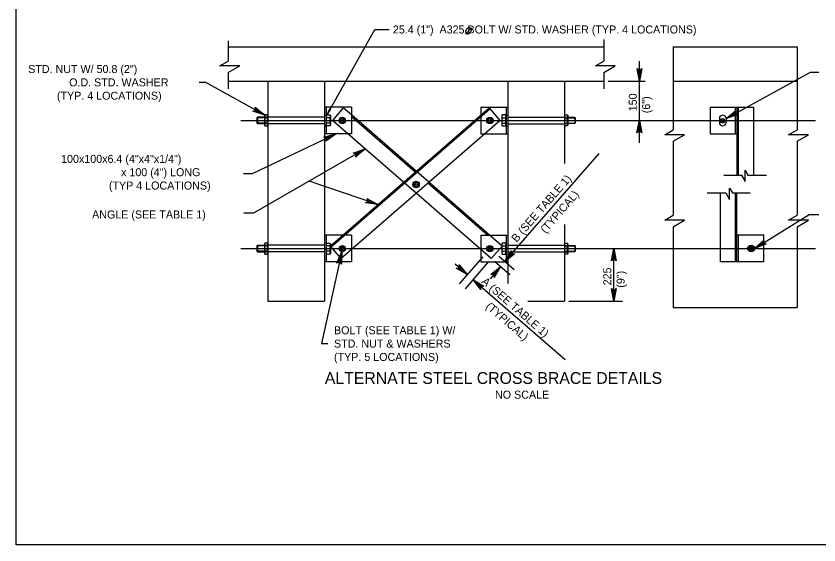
# Model space of a CAD drawing. Extents: x 638263 to 640360, y 293683 to 298655.
# Drawn here: x 639316.5 to 639617.3, y 297262.5 to 297460.7 of the extents above; entities that cross this region are included whole.
import ezdxf

# ---------------------------------------------------------------- set-up
doc = ezdxf.new("R2010")
doc.units = 0
for name, color, linetype in [('2', 7, 'Continuous'), ('3', 7, 'Continuous'), ('4', 7, 'Continuous'), ('5', 7, 'Continuous'), ('8', 7, 'Continuous')]:
    doc.layers.add(name, color=color, linetype=linetype)

msp = doc.modelspace()

# ---------------------------------------------------------------- linework, layer by layer
at = {"layer": '2'}
for p, q in [((639316.46, 297262.46), (639316.46, 297826.46)), ((640102.46, 297262.46), (639316.46, 297262.46))]:
    msp.add_line(p, q, dxfattribs=at)
at = {"layer": '3'}
for p, q in [((639450.93, 297455.71), (639456.25, 297455.71)), ((639490.65, 297416.58), (639491.98, 297416.58)), ((639491.98, 297416.58), (639500.73, 297416.58))]:
    msp.add_line(p, q, dxfattribs=at)
for points in [[(639432.73, 297423.37), (639450.93, 297455.71)], [(639550.02, 297436.36), (639549.15, 297441.02), (639549.39, 297440.67), (639549.71, 297440.48), (639550.02, 297440.43), (639550.33, 297440.48), (639550.64, 297440.67), (639550.89, 297441.02), (639550.02, 297436.36), (639550.64, 297440.67), (639550.33, 297440.48), (639550.02, 297436.36), (639550.02, 297440.43), (639549.71, 297440.48), (639550.02, 297436.36), (639549.39, 297440.67)], [(639582.5, 297422.32), (639614.1, 297439.76), (639617.31, 297439.76)], [(639550.02, 297421.6), (639550.89, 297416.94), (639550.64, 297417.3), (639550.33, 297417.48), (639550.02, 297417.54), (639549.71, 297417.48), (639549.39, 297417.3), (639549.14, 297416.94), (639550.02, 297421.6), (639549.39, 297417.3), (639549.71, 297417.48), (639550.02, 297421.6), (639550.02, 297417.54), (639550.33, 297417.48), (639550.02, 297421.6), (639550.64, 297417.3)], [(639447.29, 297410.92), (639443.68, 297407.84), (639443.87, 297408.24), (639443.87, 297408.6), (639443.76, 297408.9), (639443.56, 297409.14), (639443.25, 297409.32), (639442.81, 297409.36), (639447.29, 297410.92), (639443.25, 297409.32), (639443.56, 297409.14), (639447.29, 297410.92), (639443.76, 297408.9), (639443.87, 297408.6), (639447.29, 297410.92), (639443.87, 297408.24)], [(639452.03, 297390.07), (639426.27, 297398.84)], [(639452.03, 297390.07), (639447.34, 297390.74), (639447.76, 297390.86), (639448.03, 297391.1), (639448.18, 297391.38), (639448.23, 297391.69), (639448.16, 297392.04), (639447.9, 297392.4), (639452.03, 297390.07), (639448.16, 297392.04), (639448.23, 297391.69), (639452.03, 297390.07), (639448.18, 297391.38), (639448.03, 297391.1), (639452.03, 297390.07), (639447.76, 297390.86)], [(639593.13, 297373.57), (639613.7, 297386.35), (639617.31, 297386.35)], [(639438.5, 297372.42), (639430.87, 297337.94), (639433.34, 297337.94)], [(639438.5, 297372.42), (639438.35, 297367.68), (639438.18, 297368.08), (639437.91, 297368.33), (639437.62, 297368.45), (639437.3, 297368.46), (639436.96, 297368.35), (639436.64, 297368.05), (639438.5, 297372.42), (639436.96, 297368.35), (639437.3, 297368.46), (639438.5, 297372.42), (639437.62, 297368.45), (639437.91, 297368.33), (639438.5, 297372.42), (639438.18, 297368.08)]]:
    msp.add_lwpolyline(points, dxfattribs=at)
msp.add_lwpolyline([(639432.73, 297423.37), (639434.42, 297425.86), (639433.98, 297426.11)], close=True, dxfattribs=at)
at = {"layer": '4'}
msp.add_line((639484.85, 297453.91), (639487.09, 297456.36), dxfattribs=at)
msp.add_spline([(639486.86, 297456.12), (639486.68, 297456.25), (639486.5, 297456.3), (639486.29, 297456.32), (639486.16, 297456.32), (639485.95, 297456.27), (639485.75, 297456.18), (639485.61, 297456.1), (639485.35, 297455.89), (639485.14, 297455.62), (639485.01, 297455.37), (639484.94, 297455.14), (639484.92, 297454.92), (639484.94, 297454.74), (639485.03, 297454.47), (639485.13, 297454.34), (639485.32, 297454.19), (639485.61, 297454.12), (639485.94, 297454.13), (639486.36, 297454.32), (639486.66, 297454.58), (639486.89, 297454.9), (639487.04, 297455.23), (639487.09, 297455.6), (639487.02, 297455.84), (639486.87, 297456.12)], degree=3, dxfattribs=at)
at = {"layer": '5'}
for p, q in [((639396, 297451.41), (639396, 297443.88)), ((639536.75, 297451.93), (639536.75, 297443.88)), ((639396, 297449.16), (639536.75, 297449.16)), ((639562.71, 297449.16), (639562.71, 297418.11)), ((639562.71, 297449.16), (639609.11, 297449.16)), ((639609.11, 297449.16), (639609.11, 297418.11)), ((639392.8, 297442.03), (639396, 297443.88)), ((639400.26, 297442.03), (639392.8, 297442.03)), ((639396, 297439.57), (639400.26, 297442.03)), ((639533.55, 297442.03), (639536.75, 297443.88)), ((639541.01, 297442.03), (639533.55, 297442.03)), ((639536.75, 297439.57), (639541.01, 297442.03)), ((639396, 297439.57), (639396, 297433.46)), ((639536.75, 297439.57), (639536.75, 297433.46)), ((639396, 297436.36), (639536.75, 297436.36)), ((639410.77, 297436.36), (639410.77, 297353.88)), ((639432.03, 297436.36), (639432.03, 297353.88)), ((639500.73, 297436.36), (639500.73, 297360.44)), ((639521.99, 297436.36), (639521.99, 297405.44)), ((639562.71, 297436.36), (639609.11, 297436.36)), ((639432.03, 297426.62), (639432.03, 297416.58)), ((639442.1, 297426.62), (639432.03, 297426.62)), ((639432.65, 297426.62), (639432.65, 297416.58)), ((639434.15, 297374.52), (639493.7, 297426.29)), ((639434.47, 297374.15), (639494.02, 297425.92)), ((639439.05, 297426.29), (639434.99, 297421.62)), ((639442.1, 297423.65), (639439.05, 297426.29)), ((639442.1, 297426.62), (639442.1, 297416.58)), ((639490.65, 297426.62), (639490.65, 297423.65)), ((639490.65, 297426.62), (639500.73, 297426.62)), ((639493.7, 297426.29), (639497.77, 297421.62)), ((639500.1, 297426.62), (639500.1, 297416.58)), ((639500.73, 297426.62), (639500.73, 297416.58)), ((639576.53, 297426.62), (639592.77, 297426.62)), ((639576.53, 297426.62), (639576.53, 297416.58)), ((639585.98, 297426.62), (639585.98, 297416.58)), ((639586.57, 297426.62), (639586.57, 297401.15)), ((639587.06, 297426.62), (639587.06, 297401.15)), ((639592.77, 297426.62), (639592.77, 297401.15)), ((639400.73, 297421.6), (639532.02, 297421.6)), ((639406.89, 297422.78), (639406.73, 297422.62)), ((639406.73, 297422.62), (639406.73, 297420.58)), ((639406.89, 297422.78), (639406.89, 297420.42)), ((639410.77, 297422.78), (639406.89, 297422.78)), ((639410.77, 297422.62), (639406.89, 297422.62)), ((639409.44, 297421.6), (639410.91, 297421.6)), ((639409.74, 297423.65), (639409.59, 297423.38)), ((639409.59, 297423.38), (639409.59, 297419.83)), ((639410.77, 297422.78), (639409.59, 297422.78)), ((639410.61, 297423.65), (639409.74, 297423.65)), ((639410.61, 297422.62), (639409.74, 297422.62)), ((639410.61, 297423.65), (639410.77, 297423.38)), ((639410.77, 297423.38), (639410.77, 297419.83)), ((639432.03, 297422.85), (639410.77, 297422.85)), ((639410.77, 297422.78), (639410.77, 297420.42)), ((639432.03, 297423.57), (639432.65, 297423.57)), ((639432.65, 297422.78), (639432.6, 297422.78)), ((639432.65, 297423.37), (639432.65, 297419.83)), ((639432.73, 297423.37), (639432.65, 297423.37)), ((639432.73, 297419.56), (639432.73, 297423.65)), ((639432.73, 297423.65), (639434.09, 297423.65)), ((639434.09, 297422.62), (639432.73, 297422.62)), ((639434.09, 297423.65), (639434.25, 297423.38)), ((639434.25, 297423.38), (639434.25, 297419.83)), ((639440.78, 297416.58), (639434.99, 297421.62)), ((639438.21, 297369.84), (639497.77, 297421.62)), ((639466.38, 297402.54), (639442.1, 297423.65)), ((639466.05, 297402.17), (639442.1, 297422.99)), ((639490.65, 297422.99), (639490.65, 297416.58)), ((639498.66, 297423.65), (639498.5, 297423.38)), ((639498.5, 297423.38), (639498.5, 297419.83)), ((639500.02, 297423.65), (639498.66, 297423.65)), ((639498.66, 297422.62), (639500.02, 297422.62)), ((639500.02, 297419.56), (639500.02, 297423.65)), ((639500.02, 297423.37), (639500.1, 297423.37)), ((639500.1, 297423.57), (639500.73, 297423.57)), ((639500.1, 297423.37), (639500.1, 297419.83)), ((639500.1, 297422.78), (639500.15, 297422.78)), ((639500.73, 297422.85), (639521.99, 297422.85)), ((639523.31, 297421.6), (639521.84, 297421.6)), ((639522.14, 297423.65), (639521.99, 297423.38)), ((639521.99, 297423.38), (639521.99, 297419.83)), ((639521.99, 297422.78), (639521.99, 297420.42)), ((639521.99, 297422.78), (639523.17, 297422.78)), ((639521.99, 297422.78), (639525.86, 297422.78)), ((639521.99, 297422.62), (639525.86, 297422.62)), ((639522.14, 297423.65), (639523.01, 297423.65)), ((639522.14, 297422.62), (639523.01, 297422.62)), ((639523.01, 297423.65), (639523.17, 297423.38)), ((639523.17, 297423.38), (639523.17, 297419.83)), ((639525.86, 297422.78), (639525.86, 297420.42)), ((639525.86, 297422.78), (639526.02, 297422.62)), ((639526.02, 297422.62), (639526.02, 297420.58)), ((639532.02, 297421.6), (639615.98, 297421.6)), ((639580, 297422.32), (639580, 297420.88)), ((639582.5, 297422.32), (639582.5, 297420.88)), ((639406.73, 297420.58), (639406.89, 297420.42)), ((639410.77, 297420.58), (639406.89, 297420.58)), ((639406.89, 297420.42), (639410.77, 297420.42)), ((639410.77, 297420.42), (639409.59, 297420.42)), ((639409.59, 297419.83), (639409.74, 297419.56)), ((639410.61, 297420.58), (639409.74, 297420.58)), ((639409.74, 297419.56), (639410.61, 297419.56)), ((639410.77, 297419.83), (639410.61, 297419.56)), ((639432.03, 297420.35), (639410.77, 297420.35)), ((639432.03, 297419.63), (639432.65, 297419.63)), ((639432.65, 297420.42), (639432.6, 297420.42)), ((639434.09, 297420.58), (639432.73, 297420.58)), ((639434.09, 297419.56), (639432.73, 297419.56)), ((639434.25, 297419.83), (639434.09, 297419.56)), ((639498.5, 297419.83), (639498.66, 297419.56)), ((639498.66, 297420.58), (639500.02, 297420.58)), ((639498.66, 297419.56), (639500.02, 297419.56)), ((639500.1, 297420.42), (639500.15, 297420.42)), ((639500.1, 297419.63), (639500.73, 297419.63)), ((639500.73, 297420.35), (639521.99, 297420.35)), ((639521.99, 297420.58), (639525.86, 297420.58)), ((639521.99, 297420.42), (639523.17, 297420.42)), ((639525.86, 297420.42), (639521.99, 297420.42)), ((639521.99, 297419.83), (639522.14, 297419.56)), ((639522.14, 297420.58), (639523.01, 297420.58)), ((639523.01, 297419.56), (639522.14, 297419.56)), ((639523.17, 297419.83), (639523.01, 297419.56)), ((639526.02, 297420.58), (639525.86, 297420.42)), ((639559.51, 297416.27), (639562.71, 297418.11)), ((639605.91, 297416.27), (639609.11, 297418.11)), ((639442.1, 297416.58), (639432.03, 297416.58)), ((639461.65, 297398.43), (639440.78, 297416.58)), ((639566.98, 297416.27), (639559.51, 297416.27)), ((639562.71, 297413.8), (639566.98, 297416.27)), ((639576.53, 297416.58), (639586.57, 297416.58)), ((639613.37, 297416.27), (639605.91, 297416.27)), ((639609.11, 297413.8), (639613.37, 297416.27)), ((639562.71, 297413.8), (639562.71, 297386.06)), ((639609.11, 297413.8), (639609.11, 297386.06)), ((639589.65, 297398.74), (639589.65, 297402.95)), ((639589.65, 297402.95), (639590.7, 297401.15)), ((639471.1, 297398.43), (639466.38, 297402.54)), ((639581.65, 297401.15), (639588.26, 297401.15)), ((639588.26, 297401.15), (639589.65, 297398.74)), ((639590.7, 297401.15), (639597.69, 297401.15)), ((639466.38, 297394.32), (639461.65, 297398.43)), ((639493.18, 297378.59), (639470.78, 297398.06)), ((639493.93, 297378.59), (639471.1, 297398.43)), ((639490.65, 297373.22), (639466.38, 297394.32)), ((639575.45, 297394.42), (639582.45, 297394.42)), ((639580.37, 297368.55), (639580.37, 297394.42)), ((639582.45, 297394.42), (639583.84, 297392.02)), ((639583.84, 297396.23), (639584.88, 297394.42)), ((639583.84, 297392.02), (639583.84, 297396.23)), ((639584.88, 297394.42), (639591.49, 297394.42)), ((639586.07, 297368.55), (639586.07, 297394.42)), ((639586.57, 297368.55), (639586.57, 297394.42)), ((639559.51, 297384.21), (639562.71, 297386.06)), ((639605.91, 297384.21), (639609.11, 297386.06)), ((639521.99, 297382.62), (639521.99, 297353.88)), ((639566.98, 297384.21), (639559.51, 297384.21)), ((639562.71, 297381.75), (639566.98, 297384.21)), ((639613.37, 297384.21), (639605.91, 297384.21)), ((639609.11, 297381.75), (639613.37, 297384.21)), ((639562.71, 297381.75), (639562.71, 297351.42)), ((639609.11, 297381.75), (639609.11, 297351.42)), ((639432.03, 297378.59), (639432.03, 297368.55)), ((639438.83, 297378.59), (639432.03, 297378.59)), ((639432.65, 297378.59), (639432.65, 297368.55)), ((639442.1, 297378.59), (639439.58, 297378.59)), ((639442.1, 297378.59), (639442.1, 297373.22)), ((639490.65, 297378.59), (639490.65, 297368.55)), ((639490.65, 297378.59), (639500.73, 297378.59)), ((639498.61, 297374.52), (639493.93, 297378.59)), ((639500.1, 297378.59), (639500.1, 297368.55)), ((639500.73, 297378.59), (639500.73, 297368.55)), ((639596.61, 297378.59), (639586.57, 297378.59)), ((639587.16, 297368.55), (639587.16, 297378.59)), ((639596.61, 297368.55), (639596.61, 297378.59)), ((639400.73, 297373.57), (639532.02, 297373.57)), ((639406.89, 297374.75), (639406.73, 297374.59)), ((639406.73, 297374.59), (639406.73, 297372.55)), ((639410.77, 297374.75), (639406.89, 297374.75)), ((639406.89, 297374.75), (639406.89, 297372.39)), ((639410.77, 297374.59), (639406.89, 297374.59)), ((639409.44, 297373.57), (639410.91, 297373.57)), ((639409.74, 297375.62), (639409.59, 297375.34)), ((639409.59, 297375.34), (639409.59, 297371.79)), ((639410.77, 297374.75), (639409.59, 297374.75)), ((639410.61, 297375.62), (639409.74, 297375.62)), ((639410.61, 297374.59), (639409.74, 297374.59)), ((639410.61, 297375.62), (639410.77, 297375.34)), ((639410.77, 297375.34), (639410.77, 297371.79)), ((639432.03, 297374.82), (639410.77, 297374.82)), ((639410.77, 297374.75), (639410.77, 297372.39)), ((639432.65, 297374.75), (639432.6, 297374.75)), ((639432.65, 297375.34), (639432.65, 297371.8)), ((639432.73, 297375.34), (639432.65, 297375.34)), ((639432.73, 297371.52), (639432.73, 297375.62)), ((639432.73, 297375.62), (639434.09, 297375.62)), ((639434.09, 297374.59), (639432.73, 297374.59)), ((639434.09, 297375.62), (639434.25, 297375.34)), ((639434.15, 297374.52), (639438.21, 297369.84)), ((639434.25, 297375.34), (639434.25, 297371.79)), ((639442.1, 297373.22), (639442.1, 297368.55)), ((639494.54, 297369.84), (639490.65, 297373.22)), ((639498.61, 297374.52), (639494.54, 297369.84)), ((639498.66, 297375.62), (639498.5, 297375.34)), ((639498.5, 297375.34), (639498.5, 297371.79)), ((639500.02, 297375.62), (639498.66, 297375.62)), ((639498.66, 297374.59), (639500.02, 297374.59)), ((639500.02, 297371.52), (639500.02, 297375.62)), ((639500.02, 297375.34), (639500.1, 297375.34)), ((639500.1, 297375.34), (639500.1, 297371.8)), ((639500.1, 297374.75), (639500.15, 297374.75)), ((639500.73, 297374.82), (639521.99, 297374.82)), ((639523.31, 297373.57), (639521.84, 297373.57)), ((639522.14, 297375.62), (639521.99, 297375.34)), ((639521.99, 297375.34), (639521.99, 297371.79)), ((639521.99, 297374.75), (639521.99, 297372.39)), ((639521.99, 297374.75), (639523.17, 297374.75)), ((639521.99, 297374.75), (639525.86, 297374.75)), ((639521.99, 297374.59), (639525.86, 297374.59)), ((639522.14, 297375.62), (639523.01, 297375.62)), ((639522.14, 297374.59), (639523.01, 297374.59)), ((639523.01, 297375.62), (639523.17, 297375.34)), ((639523.17, 297375.34), (639523.17, 297371.79)), ((639525.86, 297374.75), (639525.86, 297372.39)), ((639525.86, 297374.75), (639526.02, 297374.59)), ((639526.02, 297374.59), (639526.02, 297372.55)), ((639532.02, 297373.57), (639615.98, 297373.57)), ((639406.73, 297372.55), (639406.89, 297372.39)), ((639410.77, 297372.55), (639406.89, 297372.55)), ((639406.89, 297372.39), (639410.77, 297372.39)), ((639410.77, 297372.39), (639409.59, 297372.39)), ((639409.59, 297371.79), (639409.74, 297371.52)), ((639410.61, 297372.55), (639409.74, 297372.55)), ((639409.74, 297371.52), (639410.61, 297371.52)), ((639410.77, 297371.79), (639410.61, 297371.52)), ((639432.03, 297372.32), (639410.77, 297372.32)), ((639432.65, 297372.39), (639432.6, 297372.39)), ((639434.09, 297372.55), (639432.73, 297372.55)), ((639434.09, 297371.52), (639432.73, 297371.52)), ((639434.25, 297371.79), (639434.09, 297371.52)), ((639498.5, 297371.79), (639498.66, 297371.52)), ((639498.66, 297372.55), (639500.02, 297372.55)), ((639498.66, 297371.52), (639500.02, 297371.52)), ((639500.1, 297372.39), (639500.15, 297372.39)), ((639500.73, 297372.32), (639521.99, 297372.32)), ((639521.99, 297372.55), (639525.86, 297372.55)), ((639521.99, 297372.39), (639523.17, 297372.39)), ((639525.86, 297372.39), (639521.99, 297372.39)), ((639521.99, 297371.79), (639522.14, 297371.52)), ((639522.14, 297372.55), (639523.01, 297372.55)), ((639523.01, 297371.52), (639522.14, 297371.52)), ((639523.17, 297371.79), (639523.01, 297371.52)), ((639526.02, 297372.55), (639525.86, 297372.39)), ((639442.1, 297368.55), (639432.03, 297368.55)), ((639490.65, 297368.55), (639500.73, 297368.55)), ((639596.61, 297368.55), (639580.37, 297368.55)), ((639410.77, 297353.88), (639432.03, 297353.88)), ((639508.27, 297353.88), (639521.99, 297353.88)), ((639562.71, 297351.42), (639609.11, 297351.42))]:
    msp.add_line(p, q, dxfattribs=at)
for points in [[(639409.68, 297423.54), (639387.55, 297435.88), (639385.07, 297435.88)], [(639409.68, 297423.54), (639405.18, 297425.04), (639405.62, 297425.09), (639405.93, 297425.27), (639406.13, 297425.52), (639406.24, 297425.82), (639406.22, 297426.18), (639406.03, 297426.57), (639409.68, 297423.54), (639406.22, 297426.18), (639406.24, 297425.82), (639409.68, 297423.54), (639406.13, 297425.52), (639405.93, 297425.27), (639409.68, 297423.54), (639405.62, 297425.09)], [(639436.4, 297416.58), (639404.98, 297401.64), (639401.67, 297401.64)], [(639436.4, 297416.58), (639432.56, 297413.79), (639432.78, 297414.17), (639432.81, 297414.53), (639432.73, 297414.84), (639432.55, 297415.09), (639432.25, 297415.3), (639431.81, 297415.37), (639436.4, 297416.58), (639432.25, 297415.3), (639432.55, 297415.09), (639436.4, 297416.58), (639432.73, 297414.84), (639432.81, 297414.53), (639436.4, 297416.58), (639432.78, 297414.17)], [(639447.29, 297410.92), (639405.41, 297386.84), (639401.81, 297386.84)]]:
    msp.add_lwpolyline(points, dxfattribs=at)
for centre, radius in [((639438.75, 297421.6), 1.18), ((639438.75, 297421.6), 0.833), ((639438.75, 297421.6), 0.417), ((639494, 297421.6), 1.18), ((639494, 297421.6), 0.833), ((639494, 297421.6), 0.417), ((639581.22, 297421.47), 0.833), ((639581.22, 297421.47), 0.417), ((639466.38, 297397.58), 1.18), ((639466.38, 297397.58), 0.833), ((639466.38, 297397.58), 0.417), ((639438.75, 297373.57), 1.18), ((639438.75, 297373.57), 0.833), ((639438.75, 297373.57), 0.417), ((639494, 297373.57), 1.18), ((639494, 297373.57), 0.833), ((639494, 297373.57), 0.417), ((639591.88, 297373.57), 1.25), ((639591.88, 297373.57), 0.833), ((639591.88, 297373.57), 0.417)]:
    msp.add_circle(centre, radius, dxfattribs=at)
for centre, radius, start, end in [((639410.5, 297423.13), 0.915, 146, 214), ((639413.01, 297421.6), 3.42, 162.6175, 197.3825), ((639409.85, 297423.13), 0.915, 326, 34), ((639407.34, 297421.6), 3.42, 342.6175, 17.3825), ((639433.34, 297423.13), 0.915, 326, 34), ((639430.83, 297421.6), 3.42, 342.6175, 17.3825), ((639499.42, 297423.13), 0.915, 146, 214), ((639501.93, 297421.6), 3.42, 162.6175, 197.3825), ((639522.9, 297423.13), 0.915, 146, 214), ((639525.41, 297421.6), 3.42, 162.6175, 197.3825), ((639522.25, 297423.13), 0.915, 326, 34), ((639519.74, 297421.6), 3.42, 342.6175, 17.3825), ((639581.25, 297422.32), 1.25, 0, 180), ((639410.5, 297420.07), 0.915, 146, 214), ((639409.85, 297420.07), 0.915, 326, 34), ((639433.34, 297420.07), 0.915, 326, 34), ((639499.42, 297420.07), 0.915, 146, 214), ((639522.9, 297420.07), 0.915, 146, 214), ((639522.25, 297420.07), 0.915, 326, 34), ((639581.25, 297420.88), 1.25, 180, 0), ((639410.5, 297375.1), 0.915, 146, 214), ((639413.01, 297373.57), 3.42, 162.6175, 197.3825), ((639409.85, 297375.1), 0.915, 326, 34), ((639407.34, 297373.57), 3.42, 342.6175, 17.3825), ((639433.34, 297375.1), 0.915, 326, 34), ((639430.83, 297373.57), 3.42, 342.6175, 17.3825), ((639499.42, 297375.1), 0.915, 146, 214), ((639501.93, 297373.57), 3.42, 162.6175, 197.3825), ((639522.9, 297375.1), 0.915, 146, 214), ((639525.41, 297373.57), 3.42, 162.6175, 197.3825), ((639522.25, 297375.1), 0.915, 326, 34), ((639519.74, 297373.57), 3.42, 342.6175, 17.3825), ((639410.5, 297372.03), 0.915, 146, 214), ((639409.85, 297372.03), 0.915, 326, 34), ((639433.34, 297372.03), 0.915, 326, 34), ((639499.42, 297372.03), 0.915, 146, 214), ((639522.9, 297372.03), 0.915, 146, 214), ((639522.25, 297372.03), 0.915, 326, 34)]:
    msp.add_arc(centre, radius, start, end, dxfattribs=at)
at = {"layer": '8'}
for p, q in [((639550.02, 297413.16), (639550.02, 297443.77)), ((639538.31, 297436.36), (639552.16, 297436.36)), ((639538.31, 297421.6), (639552.16, 297421.6)), ((639499.65, 297368.66), (639534.97, 297409.27)), ((639523.55, 297373.57), (639541.46, 297373.57)), ((639540.46, 297353.88), (639540.46, 297373.57)), ((639491.36, 297370.53), (639482.55, 297360.4)), ((639497.33, 297370.67), (639503.05, 297365.7)), ((639485.5, 297363.79), (639480.97, 297367.73)), ((639493.51, 297368.66), (639484.7, 297358.52)), ((639498.04, 297366.8), (639494.1, 297362.27)), ((639495.72, 297368.81), (639501.44, 297363.84)), ((639487.66, 297361.92), (639522.16, 297331.92)), ((639523.55, 297353.88), (639543.76, 297353.88))]:
    msp.add_line(p, q, dxfattribs=at)
for points in [[(639582.5, 297422.32), (639586.16, 297425.34), (639585.97, 297424.94), (639585.95, 297424.58), (639586.06, 297424.28), (639586.26, 297424.03), (639586.57, 297423.85), (639587, 297423.81), (639582.5, 297422.32), (639586.57, 297423.85), (639586.26, 297424.03), (639582.5, 297422.32), (639586.06, 297424.28), (639585.95, 297424.58), (639582.5, 297422.32), (639585.97, 297424.94)], [(639593.13, 297373.57), (639596.63, 297376.77), (639596.46, 297376.37), (639596.46, 297376.01), (639596.58, 297375.71), (639596.79, 297375.48), (639597.12, 297375.31), (639597.55, 297375.29), (639593.13, 297373.57), (639597.12, 297375.31), (639596.79, 297375.48), (639593.13, 297373.57), (639596.58, 297375.71), (639596.46, 297376.01), (639593.13, 297373.57), (639596.46, 297376.37)], [(639540.46, 297373.57), (639541.34, 297368.91), (639541.09, 297369.27), (639540.78, 297369.45), (639540.46, 297369.51), (639540.15, 297369.45), (639539.84, 297369.27), (639539.59, 297368.91), (639540.46, 297373.57), (639539.84, 297369.27), (639540.15, 297369.45), (639540.46, 297373.57), (639540.46, 297369.51), (639540.78, 297369.45), (639540.46, 297373.57), (639541.09, 297369.27)], [(639499.65, 297368.66), (639502.05, 297372.74), (639502, 297372.31), (639502.12, 297371.97), (639502.32, 297371.72), (639502.59, 297371.56), (639502.95, 297371.49), (639503.37, 297371.6), (639499.65, 297368.66), (639502.95, 297371.49), (639502.59, 297371.56), (639499.65, 297368.66), (639502.32, 297371.72), (639502.12, 297371.97), (639499.65, 297368.66), (639502, 297372.31)], [(639485.5, 297363.79), (639481.41, 297366.19), (639481.85, 297366.14), (639482.19, 297366.26), (639482.44, 297366.46), (639482.6, 297366.73), (639482.66, 297367.09), (639482.56, 297367.51), (639485.5, 297363.79), (639482.66, 297367.09), (639482.6, 297366.73), (639485.5, 297363.79), (639482.44, 297366.46), (639482.19, 297366.26), (639485.5, 297363.79), (639481.85, 297366.14)], [(639498.04, 297366.8), (639495.64, 297362.71), (639495.69, 297363.14), (639495.57, 297363.49), (639495.37, 297363.73), (639495.1, 297363.89), (639494.75, 297363.96), (639494.32, 297363.85), (639498.04, 297366.8), (639494.75, 297363.96), (639495.1, 297363.89), (639498.04, 297366.8), (639495.37, 297363.73), (639495.57, 297363.49), (639498.04, 297366.8), (639495.69, 297363.14)], [(639487.66, 297361.92), (639491.75, 297359.52), (639491.31, 297359.57), (639490.97, 297359.46), (639490.72, 297359.26), (639490.56, 297358.98), (639490.49, 297358.63), (639490.6, 297358.21), (639487.66, 297361.92), (639490.49, 297358.63), (639490.56, 297358.98), (639487.66, 297361.92), (639490.72, 297359.26), (639490.97, 297359.46), (639487.66, 297361.92), (639491.31, 297359.57)], [(639540.46, 297353.88), (639539.59, 297358.54), (639539.84, 297358.19), (639540.15, 297358), (639540.46, 297357.95), (639540.78, 297358), (639541.09, 297358.19), (639541.34, 297358.54), (639540.46, 297353.88), (639541.09, 297358.19), (639540.78, 297358), (639540.46, 297353.88), (639540.46, 297357.95), (639540.15, 297358), (639540.46, 297353.88), (639539.84, 297358.19)]]:
    msp.add_lwpolyline(points, dxfattribs=at)

# ---------------------------------------------------------------- texts
at = {"layer": '3'}
for s, height, p in [('25.4 (1")  A325 BOLT W/ STD. WASHER (TYP. 4 LOCATIONS)', 3, (639457.66, 297454.21)), (' STD. NUT W/ 50.8 (2")', 3, (639319.88, 297439.38)), ('O.D. STD. WASHER', 3, (639336.34, 297434.38)), ('(TYP. 4 LOCATIONS)', 3, (639331.78, 297429.38)), ('100x100x6.4 (4"x4"x1/4")', 3, (639333.33, 297405.7)), ('x 100 (4") LONG', 3, (639355.8, 297400.7)), ('(TYP 4 LOCATIONS)', 3, (639351.24, 297395.7)), ('ANGLE (SEE TABLE 1)', 3, (639344.96, 297384.85)), ('BOLT (SEE TABLE 1) W/', 3, (639435.6, 297341.44)), ('STD. NUT & WASHERS', 3, (639435.6, 297336.44)), ('(TYP. 5 LOCATIONS)', 3, (639435.6, 297331.44)), ('ALTERNATE STEEL CROSS BRACE DETAILS', 4.4292, (639432.16, 297322.82)), ('NO SCALE', 3, (639495.94, 297317.3))]:
    msp.add_text(s, height=height, dxfattribs=at).set_placement(p)
for s, p in [('150', (639549.07, 297425.05)), ('(6")', (639554.07, 297424.31)), ('225', (639539.5, 297359.77)), ('(9")', (639544.5, 297358.9))]:
    msp.add_text(s, height=3, rotation=90, dxfattribs=at).set_placement(p)
at = {"layer": '8'}
for s, rotation, p in [(' B (SEE TABLE 1)', 48.9947, (639503.3, 297374.87)), ('(TYPICAL)', 48.9947, (639514.9, 297379.06)), (' A (SEE TABLE 1)', 318.996, (639489.79, 297361.57)), ('(TYPICAL)', 318.996, (639492.2, 297351.51))]:
    msp.add_text(s, height=3, rotation=rotation, dxfattribs=at).set_placement(p)

doc.saveas('drawing.dxf')
